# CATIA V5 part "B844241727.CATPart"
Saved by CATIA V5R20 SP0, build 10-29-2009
Part number: B844241727
Revision: 2
Definition: design
Nomenclature: B844241727
Source: made
Description: NOT SPECIFIED
Bounding box of the stored display mesh (mm): x -20.5 to 20.5, y -20.5 to 20.5, z -17 to 27
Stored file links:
  C:\Users\Utente\Desktop\3D files B844\B844241727.CATPart
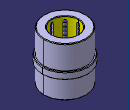
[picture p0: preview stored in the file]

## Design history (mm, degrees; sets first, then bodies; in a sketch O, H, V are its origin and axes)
Body1 "MANIFOLD_SOLID_BREP #38" (main body)
  Solid1: solid without history
Body2 "MANIFOLD_SOLID_BREP #76"
  Solid2: solid without history
Body3 "MANIFOLD_SOLID_BREP #114"
  Solid3: solid without history
Body4 "MANIFOLD_SOLID_BREP #152"
  Solid4: solid without history
Body5 "MANIFOLD_SOLID_BREP #190"
  Solid5: solid without history
Body6 "MANIFOLD_SOLID_BREP #228"
  Solid6: solid without history
Body7 "MANIFOLD_SOLID_BREP #266"
  Solid7: solid without history
Body8 "MANIFOLD_SOLID_BREP #304"
  Solid8: solid without history
Body9 "MANIFOLD_SOLID_BREP #2358"
  Solid9: solid without history
Body10 "MANIFOLD_SOLID_BREP #2396"
  Solid10: solid without history
Body11 "MANIFOLD_SOLID_BREP #2434"
  Solid11: solid without history
Body12 "MANIFOLD_SOLID_BREP #2472"
  Solid12: solid without history
Body13 "MANIFOLD_SOLID_BREP #2510"
  Solid13: solid without history
Body14 "MANIFOLD_SOLID_BREP #2548"
  Solid14: solid without history
Body15 "MANIFOLD_SOLID_BREP #2586"
  Solid15: solid without history
Body16 "MANIFOLD_SOLID_BREP #2624"
  Solid16: solid without history
Body17 "MANIFOLD_SOLID_BREP #2662"
  Solid17: solid without history
Body18 "MANIFOLD_SOLID_BREP #2700"
  Solid18: solid without history
Body19 "MANIFOLD_SOLID_BREP #2738"
  Solid19: solid without history
Body20 "MANIFOLD_SOLID_BREP #2776"
  Solid20: solid without history
Body21 "MANIFOLD_SOLID_BREP #2814"
  Solid21: solid without history
Body22 "MANIFOLD_SOLID_BREP #2852"
  Solid22: solid without history
Body23 "MANIFOLD_SOLID_BREP #2890"
  Solid23: solid without history
Body24 "MANIFOLD_SOLID_BREP #2928"
  Solid24: solid without history
Body25 "MANIFOLD_SOLID_BREP #2966"
  Solid25: solid without history
Body26 "MANIFOLD_SOLID_BREP #3004"
  Solid26: solid without history
Body27 "MANIFOLD_SOLID_BREP #3042"
  Solid27: solid without history
Body28 "MANIFOLD_SOLID_BREP #3080"
  Solid28: solid without history
Body29 "MANIFOLD_SOLID_BREP #3118"
  Solid29: solid without history
Body30 "MANIFOLD_SOLID_BREP #3156"
  Solid30: solid without history
Body31 "MANIFOLD_SOLID_BREP #3194"
  Solid31: solid without history
Body32 "MANIFOLD_SOLID_BREP #3232"
  Solid32: solid without history
Body33 "MANIFOLD_SOLID_BREP #3270"
  Solid33: solid without history
Body34 "MANIFOLD_SOLID_BREP #3308"
  Solid34: solid without history
Body35 "MANIFOLD_SOLID_BREP #3346"
  Solid35: solid without history
Body36 "MANIFOLD_SOLID_BREP #3384"
  Solid36: solid without history
Body37 "MANIFOLD_SOLID_BREP #3422"
  Solid37: solid without history
Body38 "MANIFOLD_SOLID_BREP #3460"
  Solid38: solid without history
Body39 "MANIFOLD_SOLID_BREP #3498"
  Solid39: solid without history
Body40 "MANIFOLD_SOLID_BREP #3536"
  Solid40: solid without history
Body41 "MANIFOLD_SOLID_BREP #3574"
  Solid41: solid without history
Body42 "MANIFOLD_SOLID_BREP #3612"
  Solid42: solid without history
Body43 "MANIFOLD_SOLID_BREP #3650"
  Solid43: solid without history
Body44 "MANIFOLD_SOLID_BREP #3688"
  Solid44: solid without history
Body45 "MANIFOLD_SOLID_BREP #3726"
  Solid45: solid without history
Body46 "MANIFOLD_SOLID_BREP #3764"
  Solid46: solid without history
Body47 "MANIFOLD_SOLID_BREP #3802"
  Solid47: solid without history
Body48 "MANIFOLD_SOLID_BREP #3840"
  Solid48: solid without history
Body49 "MANIFOLD_SOLID_BREP #3878"
  Solid49: solid without history
Body50 "MANIFOLD_SOLID_BREP #3916"
  Solid50: solid without history
Body51 "MANIFOLD_SOLID_BREP #3954"
  Solid51: solid without history
Body52 "MANIFOLD_SOLID_BREP #3992"
  Solid52: solid without history
Body53 "MANIFOLD_SOLID_BREP #4030"
  Solid53: solid without history
Body54 "MANIFOLD_SOLID_BREP #4068"
  Solid54: solid without history
Body55 "MANIFOLD_SOLID_BREP #4106"
  Solid55: solid without history
Body56 "MANIFOLD_SOLID_BREP #4144"
  Solid56: solid without history
Body57 "MANIFOLD_SOLID_BREP #4182"
  Solid57: solid without history
Body58 "MANIFOLD_SOLID_BREP #4220"
  Solid58: solid without history
Body59 "MANIFOLD_SOLID_BREP #4258"
  Solid59: solid without history
Body60 "MANIFOLD_SOLID_BREP #4296"
  Solid60: solid without history
Body61 "MANIFOLD_SOLID_BREP #4334"
  Solid61: solid without history
Body62 "MANIFOLD_SOLID_BREP #4372"
  Solid62: solid without history
Body63 "MANIFOLD_SOLID_BREP #4410"
  Solid63: solid without history
Body64 "MANIFOLD_SOLID_BREP #4448"
  Solid64: solid without history
Body65 "MANIFOLD_SOLID_BREP #4486"
  Solid65: solid without history
Body66 "MANIFOLD_SOLID_BREP #4524"
  Solid66: solid without history
Body67 "MANIFOLD_SOLID_BREP #4562"
  Solid67: solid without history
Body68 "MANIFOLD_SOLID_BREP #4600"
  Solid68: solid without history
Body69 "MANIFOLD_SOLID_BREP #4638"
  Solid69: solid without history
Body70 "MANIFOLD_SOLID_BREP #4676"
  Solid70: solid without history
Body71 "MANIFOLD_SOLID_BREP #4714"
  Solid71: solid without history
Body72 "MANIFOLD_SOLID_BREP #4752"
  Solid72: solid without history
Body73 "MANIFOLD_SOLID_BREP #4790"
  Solid73: solid without history
Body74 "MANIFOLD_SOLID_BREP #4828"
  Solid74: solid without history
Body75 "MANIFOLD_SOLID_BREP #4866"
  Solid75: solid without history
Body76 "MANIFOLD_SOLID_BREP #4904"
  Solid76: solid without history
Body77 "MANIFOLD_SOLID_BREP #4942"
  Solid77: solid without history
Body78 "MANIFOLD_SOLID_BREP #4980"
  Solid78: solid without history
Body79 "MANIFOLD_SOLID_BREP #5018"
  Solid79: solid without history
Body80 "MANIFOLD_SOLID_BREP #5056"
  Solid80: solid without history
Body81 "MANIFOLD_SOLID_BREP #5094"
  Solid81: solid without history
Body82 "MANIFOLD_SOLID_BREP #5132"
  Solid82: solid without history
Body83 "MANIFOLD_SOLID_BREP #5170"
  Solid83: solid without history
Body84 "MANIFOLD_SOLID_BREP #5208"
  Solid84: solid without history
Body85 "MANIFOLD_SOLID_BREP #5246"
  Solid85: solid without history
Body86 "MANIFOLD_SOLID_BREP #5284"
  Solid86: solid without history
Body87 "MANIFOLD_SOLID_BREP #5322"
  Solid87: solid without history
Body88 "MANIFOLD_SOLID_BREP #5360"
  Solid88: solid without history
Body89 "MANIFOLD_SOLID_BREP #5398"
  Solid89: solid without history
Body90 "MANIFOLD_SOLID_BREP #5436"
  Solid90: solid without history
Body91 "MANIFOLD_SOLID_BREP #5474"
  Solid91: solid without history
Body92 "MANIFOLD_SOLID_BREP #5512"
  Solid92: solid without history
Body93 "MANIFOLD_SOLID_BREP #5550"
  Solid93: solid without history
Body94 "MANIFOLD_SOLID_BREP #5588"
  Solid94: solid without history
Body95 "MANIFOLD_SOLID_BREP #5626"
  Solid95: solid without history
Body96 "MANIFOLD_SOLID_BREP #5664"
  Solid96: solid without history
Body97 "MANIFOLD_SOLID_BREP #5702"
  Solid97: solid without history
